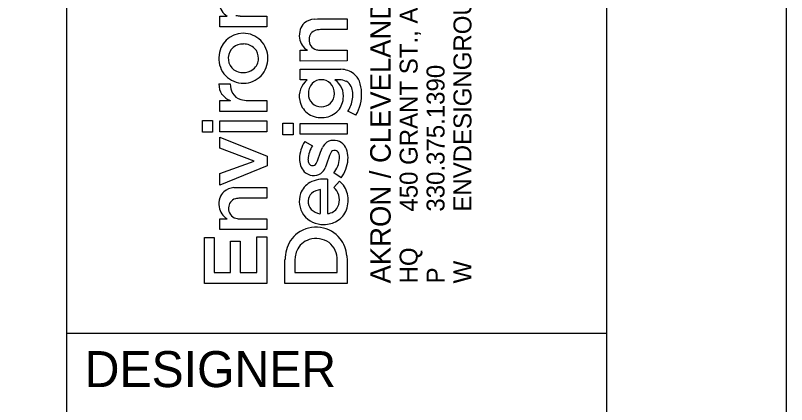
# Model space of a CAD drawing. Extents: x -0.3 to 34, y 0 to 22.
# Drawn here: x 31.857 to 34, y 2.302 to 3.382 of the extents above; entities that cross this region are included whole.
import ezdxf

# ---------------------------------------------------------------- set-up
doc = ezdxf.new("R2010")
doc.units = 0
for name, color, linetype in [('PM_X_CL_Double_Solid', 7, 'Continuous'), ('PM_X_CL_Pass_Proh_Lt', 7, 'Continuous'), ('PV_X_EOP', 7, 'Continuous')]:
    doc.layers.add(name, color=color, linetype=linetype)

msp = doc.modelspace()

# ---------------------------------------------------------------- linework, layer by layer
at = {"layer": 'PM_X_CL_Double_Solid'}
msp.add_lwpolyline([(0, 0), (34, 0), (34, 22), (0, 22)], close=True, dxfattribs=at)
at = {"layer": 'PM_X_CL_Pass_Proh_Lt'}
for p, q in [((32, 0.5), (32, 21.5)), ((32, 2.5), (33.5, 2.5))]:
    msp.add_line(p, q, dxfattribs=at)
msp.add_lwpolyline([(1.5, 21.5), (33.5, 21.5), (33.5, 0.5), (1.5, 0.5)], close=True, dxfattribs=at)
at = {"layer": 'PV_X_EOP'}
for p, q in [((32.4254, 3.3509), (32.4254, 3.3807)), ((32.4254, 3.3807), (32.4455, 3.3807)), ((32.4822, 3.3807), (32.5557, 3.3807)), ((32.5557, 3.3807), (32.5557, 3.351)), ((32.6878, 3.3722), (32.6963, 3.3727)), ((32.6963, 3.3727), (32.7792, 3.3727)), ((32.7792, 3.3727), (32.7792, 3.3429)), ((32.5557, 3.351), (32.4254, 3.3509)), ((32.7792, 3.3429), (32.7048, 3.3428)), ((32.6489, 3.2557), (32.6489, 3.2855)), ((32.6489, 3.2855), (32.669, 3.2855)), ((32.7057, 3.2855), (32.7791, 3.2855)), ((32.7791, 3.2855), (32.7792, 3.2558)), ((32.7792, 3.2558), (32.6489, 3.2557)), ((32.6489, 3.2034), (32.6489, 3.2332)), ((32.6489, 3.2332), (32.7524, 3.2332)), ((32.7524, 3.2332), (32.7619, 3.2329)), ((32.6684, 3.2034), (32.6489, 3.2034)), ((32.7576, 3.2036), (32.7449, 3.2036)), ((32.423, 3.1919), (32.4545, 3.1919)), ((32.4254, 3.1159), (32.4254, 3.1458)), ((32.4254, 3.1458), (32.4547, 3.1458)), ((32.5041, 3.1458), (32.5557, 3.1457)), ((32.5557, 3.1457), (32.5556, 3.1159)), ((32.5556, 3.1159), (32.4254, 3.1159)), ((32.8036, 3.1049), (32.7812, 3.116)), ((32.3771, 3.0582), (32.3771, 3.0903)), ((32.3771, 3.0903), (32.4054, 3.0903)), ((32.4054, 3.0903), (32.4054, 3.0582)), ((32.4254, 3.0594), (32.4254, 3.0893)), ((32.4254, 3.0893), (32.5557, 3.0893)), ((32.5557, 3.0893), (32.5557, 3.0594)), ((32.6005, 3.0511), (32.6005, 3.0832)), ((32.6005, 3.0832), (32.6289, 3.0832)), ((32.6289, 3.0832), (32.6289, 3.0511)), ((32.6489, 3.0523), (32.6489, 3.0822)), ((32.6489, 3.0822), (32.7792, 3.0822)), ((32.7792, 3.0822), (32.7792, 3.0523)), ((32.4054, 3.0582), (32.3771, 3.0582)), ((32.5557, 3.0594), (32.4254, 3.0594)), ((32.4254, 3.0133), (32.4254, 3.0446)), ((32.4254, 3.0446), (32.5567, 2.9913)), ((32.6289, 3.0511), (32.6005, 3.0511)), ((32.7792, 3.0523), (32.6489, 3.0523)), ((32.6615, 3.0321), (32.6827, 3.0203)), ((32.5212, 2.978), (32.4254, 3.0133)), ((32.6967, 2.9787), (32.7048, 3.0026)), ((32.7048, 3.0026), (32.7104, 3.0153)), ((32.7334, 3.001), (32.7298, 2.9933)), ((32.5567, 2.9913), (32.5567, 2.9644)), ((32.693, 2.9712), (32.6967, 2.9787)), ((32.7298, 2.9933), (32.7221, 2.9688)), ((32.4254, 2.9429), (32.5212, 2.978)), ((32.5567, 2.9644), (32.4254, 2.9109)), ((32.7221, 2.9688), (32.7182, 2.9592)), ((32.4254, 2.9109), (32.4254, 2.9429)), ((32.7621, 2.9314), (32.742, 2.9447)), ((32.7245, 2.9275), (32.7246, 2.8319)), ((32.7423, 2.9046), (32.7577, 2.922)), ((32.4644, 2.904), (32.4729, 2.9044)), ((32.4729, 2.9044), (32.5557, 2.9044)), ((32.5557, 2.9044), (32.5557, 2.8746)), ((32.7049, 2.8318), (32.7049, 2.8983)), ((32.5557, 2.8746), (32.4814, 2.8746)), ((32.7036, 2.8317), (32.7049, 2.8318)), ((32.4254, 2.7875), (32.4254, 2.8173)), ((32.4254, 2.8173), (32.4455, 2.8173)), ((32.4822, 2.8173), (32.5557, 2.8173)), ((32.5557, 2.8173), (32.5557, 2.7876)), ((32.5557, 2.7876), (32.4254, 2.7875)), ((32.383, 2.6379), (32.383, 2.766)), ((32.383, 2.766), (32.4101, 2.766)), ((32.4101, 2.766), (32.4101, 2.6683)), ((32.5286, 2.6683), (32.5286, 2.7672)), ((32.5286, 2.7672), (32.5557, 2.7672)), ((32.5557, 2.7672), (32.5557, 2.6379)), ((32.455, 2.6683), (32.455, 2.7549)), ((32.455, 2.7549), (32.4822, 2.7549)), ((32.4822, 2.7549), (32.4822, 2.6683)), ((32.6064, 2.638), (32.6064, 2.704)), ((32.6347, 2.7118), (32.6341, 2.7023)), ((32.6341, 2.7023), (32.6341, 2.6684)), ((32.7515, 2.6683), (32.7515, 2.7024)), ((32.7785, 2.715), (32.7792, 2.7021)), ((32.7792, 2.7021), (32.7792, 2.638)), ((32.4101, 2.6683), (32.455, 2.6683)), ((32.4822, 2.6683), (32.5286, 2.6683)), ((32.6341, 2.6684), (32.7515, 2.6683)), ((32.5557, 2.6379), (32.383, 2.6379)), ((32.7792, 2.638), (32.6064, 2.638))]:
    msp.add_line(p, q, dxfattribs=at)
for points in [[(32.4254, 3.3509), (32.4254, 3.3807), (32.4455, 3.3807)], [(32.4822, 3.3807), (32.5557, 3.3807), (32.5557, 3.351), (32.4254, 3.3509)], [(32.6878, 3.3722), (32.6963, 3.3727), (32.7792, 3.3727), (32.7792, 3.3429), (32.7048, 3.3428)], [(32.6489, 3.2557), (32.6489, 3.2855), (32.669, 3.2855)], [(32.7057, 3.2855), (32.7791, 3.2855), (32.7792, 3.2558), (32.6489, 3.2557)], [(32.6684, 3.2034), (32.6489, 3.2034), (32.6489, 3.2332), (32.7524, 3.2332), (32.7619, 3.2329)], [(32.7576, 3.2036), (32.7449, 3.2036)], [(32.423, 3.1919), (32.4545, 3.1919)], [(32.4254, 3.1159), (32.4254, 3.1458), (32.4547, 3.1458)], [(32.5041, 3.1458), (32.5557, 3.1457), (32.5556, 3.1159), (32.4254, 3.1159)], [(32.8036, 3.1049), (32.7812, 3.116)], [(32.6615, 3.0321), (32.6827, 3.0203)], [(32.693, 2.9712), (32.6967, 2.9787), (32.7048, 3.0026), (32.7104, 3.0153)], [(32.7334, 3.001), (32.7298, 2.9933), (32.7221, 2.9688), (32.7182, 2.9592)], [(32.7621, 2.9314), (32.742, 2.9447)], [(32.7245, 2.9275), (32.7246, 2.8319)], [(32.7423, 2.9046), (32.7577, 2.922)], [(32.4644, 2.904), (32.4729, 2.9044), (32.5557, 2.9044), (32.5557, 2.8746), (32.4814, 2.8746)], [(32.7036, 2.8317), (32.7049, 2.8318), (32.7049, 2.8983)], [(32.4254, 2.7875), (32.4254, 2.8173), (32.4455, 2.8173)], [(32.4822, 2.8173), (32.5557, 2.8173), (32.5557, 2.7876), (32.4254, 2.7875)], [(32.7785, 2.715), (32.7792, 2.7021), (32.7792, 2.638), (32.6064, 2.638)], [(32.6064, 2.638), (32.6064, 2.704)], [(32.6347, 2.7118), (32.6341, 2.7023), (32.6341, 2.6684), (32.7515, 2.6683), (32.7515, 2.7024)]]:
    msp.add_lwpolyline(points, dxfattribs=at)
for points in [[(32.3771, 3.0582), (32.3771, 3.0903), (32.4054, 3.0903), (32.4054, 3.0582)], [(32.4254, 3.0594), (32.4254, 3.0893), (32.5557, 3.0893), (32.5557, 3.0594)], [(32.6005, 3.0511), (32.6005, 3.0832), (32.6289, 3.0832), (32.6289, 3.0511)], [(32.6489, 3.0523), (32.6489, 3.0822), (32.7792, 3.0822), (32.7792, 3.0523)], [(32.4254, 2.9109), (32.4254, 2.9429), (32.5212, 2.978), (32.4254, 3.0133), (32.4254, 3.0446), (32.5567, 2.9913), (32.5567, 2.9644)], [(32.383, 2.6379), (32.383, 2.766), (32.4101, 2.766), (32.4101, 2.6683), (32.455, 2.6683), (32.455, 2.7549), (32.4822, 2.7549), (32.4822, 2.6683), (32.5286, 2.6683), (32.5286, 2.7672), (32.5557, 2.7672), (32.5557, 2.6379)]]:
    msp.add_lwpolyline(points, close=True, dxfattribs=at)
for centre, radius, start, end in [((32.4703, 3.4214), 0.0476, 188.9646, 238.6987), ((32.4703, 3.4214), 0.0476, 188.9646, 238.6987), ((32.4818, 3.4229), 0.0421, 254.0891, 270.5284), ((32.4818, 3.4229), 0.0421, 254.0891, 270.5284), ((32.6922, 3.3225), 0.0499, 94.9706, 130.2248), ((32.6922, 3.3225), 0.0499, 94.9706, 130.2248), ((32.7022, 3.3264), 0.056, 162.274, 187.7917), ((32.7022, 3.3264), 0.056, 162.274, 187.7917), ((32.6869, 3.3309), 0.0402, 132.2238, 161.6823), ((32.6869, 3.3309), 0.0402, 132.2238, 161.6823), ((32.7045, 3.2968), 0.046, 89.6051, 105.3303), ((32.7045, 3.2968), 0.046, 89.6051, 105.3303), ((32.4901, 3.2654), 0.0674, 89.8476, 179.6405), ((32.4901, 3.2654), 0.0674, 89.8476, 179.6405), ((32.4906, 3.2647), 0.0681, 359.5401, 90.2114), ((32.4906, 3.2647), 0.0681, 359.5401, 90.2114), ((32.6983, 3.3169), 0.025, 103.6868, 182.214), ((32.6983, 3.3169), 0.025, 103.6868, 182.214), ((32.4892, 3.2626), 0.0404, 87.0481, 175.5726), ((32.4892, 3.2626), 0.0404, 87.0481, 175.5726), ((32.492, 3.26), 0.043, 45.8426, 90.9801), ((32.492, 3.26), 0.043, 45.8426, 90.9801), ((32.6937, 3.3262), 0.0476, 188.9646, 238.6987), ((32.6937, 3.3262), 0.0476, 188.9646, 238.6987), ((32.7008, 3.3138), 0.0276, 175.5844, 255.1382), ((32.7008, 3.3138), 0.0276, 175.5844, 255.1382), ((32.4946, 3.2642), 0.0382, 357.8857, 44.159), ((32.4946, 3.2642), 0.0382, 357.8857, 44.159), ((32.7053, 3.3277), 0.0421, 254.0891, 270.5284), ((32.7053, 3.3277), 0.0421, 254.0891, 270.5284), ((32.4908, 3.2621), 0.0682, 176.8344, 270.4038), ((32.4908, 3.2621), 0.0682, 176.8344, 270.4038), ((32.4873, 3.2625), 0.0385, 175.1538, 221.1471), ((32.4873, 3.2625), 0.0385, 175.1538, 221.1471), ((32.4912, 3.2614), 0.0675, 270.0624, 2.3776), ((32.4912, 3.2614), 0.0675, 270.0624, 2.3776), ((32.4945, 3.2632), 0.0383, 308.2894, 359.4347), ((32.4945, 3.2632), 0.0383, 308.2894, 359.4347), ((32.4892, 3.2661), 0.0423, 223.0999, 268.8089), ((32.4892, 3.2661), 0.0423, 223.0999, 268.8089), ((32.491, 3.2679), 0.0442, 266.5651, 308.0608), ((32.491, 3.2679), 0.0442, 266.5651, 308.0608), ((32.7591, 3.1679), 0.065, 53.4034, 87.4906), ((32.7591, 3.1679), 0.065, 53.4034, 87.4906), ((32.7652, 3.1804), 0.0514, 21.6075, 50.5577), ((32.7652, 3.1804), 0.0514, 21.6075, 50.5577), ((32.7029, 3.1581), 0.0569, 127.3748, 192.2247), ((32.7029, 3.1581), 0.0569, 127.3748, 192.2247), ((32.7114, 3.166), 0.0401, 137.4674, 182.3324), ((32.7114, 3.166), 0.0401, 137.4674, 182.3324), ((32.7069, 3.1693), 0.0346, 88.473, 136.4256), ((32.7069, 3.1693), 0.0346, 88.473, 136.4256), ((32.7081, 3.1696), 0.0342, 44.2719, 90.4762), ((32.7081, 3.1696), 0.0342, 44.2719, 90.4762), ((32.7037, 3.166), 0.04, 358.5714, 43.5376), ((32.7037, 3.166), 0.04, 358.5714, 43.5376), ((32.7142, 3.1583), 0.0547, 352.1125, 55.923), ((32.7142, 3.1583), 0.0547, 352.1125, 55.923), ((32.7567, 3.1572), 0.0463, 65.0169, 88.8011), ((32.7567, 3.1572), 0.0463, 65.0169, 88.8011), ((32.7626, 3.1716), 0.0309, 26.2681, 63.803), ((32.7626, 3.1716), 0.0309, 26.2681, 63.803), ((32.7307, 3.1671), 0.0884, 1.1514, 21.3627), ((32.7307, 3.1671), 0.0884, 1.1514, 21.3627), ((32.4662, 3.1888), 0.0433, 175.8731, 216.3475), ((32.4662, 3.1888), 0.0433, 175.8731, 216.3475), ((32.5009, 3.1895), 0.0464, 176.9688, 209.6064), ((32.5009, 3.1895), 0.0464, 176.9688, 209.6064), ((32.7357, 3.1615), 0.0595, 349.3073, 23.4307), ((32.7357, 3.1615), 0.0595, 349.3073, 23.4307), ((32.4747, 3.1972), 0.0551, 218.0981, 248.7907), ((32.4747, 3.1972), 0.0551, 218.0981, 248.7907), ((32.4951, 3.1881), 0.0408, 211.9447, 253.2028), ((32.4951, 3.1881), 0.0408, 211.9447, 253.2028), ((32.7065, 3.1637), 0.0351, 178.8821, 271.0837), ((32.7065, 3.1637), 0.0351, 178.8821, 271.0837), ((32.7082, 3.164), 0.0355, 268.2788, 1.5502), ((32.7082, 3.164), 0.0355, 268.2788, 1.5502), ((32.7099, 3.1571), 0.0589, 313.742, 353.8554), ((32.7099, 3.1571), 0.0589, 313.742, 353.8554), ((32.7074, 3.1633), 0.0877, 327.3149, 351.5748), ((32.7074, 3.1633), 0.0877, 327.3149, 351.5748), ((32.7054, 3.1624), 0.1138, 329.6388, 3.26), ((32.7054, 3.1624), 0.1138, 329.6388, 3.26), ((32.5047, 3.2165), 0.0707, 252.4655, 269.573), ((32.5047, 3.2165), 0.0707, 252.4655, 269.573), ((32.7046, 3.157), 0.0584, 190.7518, 231.2892), ((32.7046, 3.157), 0.0584, 190.7518, 231.2892), ((32.7063, 3.1611), 0.0627, 232.4606, 272.5902), ((32.7063, 3.1611), 0.0627, 232.4606, 272.5902), ((32.7095, 3.159), 0.0605, 269.6361, 312.7088), ((32.7095, 3.159), 0.0605, 269.6361, 312.7088), ((32.7364, 2.9826), 0.0897, 146.531, 178.7571), ((32.7364, 2.9826), 0.0897, 146.531, 178.7571), ((32.7466, 2.9971), 0.0405, 125.5118, 153.4159), ((32.7466, 2.9971), 0.0405, 125.5118, 153.4159), ((32.7406, 3.0026), 0.0326, 80.1719, 122.5197), ((32.7406, 3.0026), 0.0326, 80.1719, 122.5197), ((32.7428, 2.9982), 0.0367, 47.7934, 84.6892), ((32.7428, 2.9982), 0.0367, 47.7934, 84.6892), ((32.7379, 2.9946), 0.0427, 14.9966, 46.2063), ((32.7379, 2.9946), 0.0427, 14.9966, 46.2063), ((32.7452, 2.9789), 0.0749, 146.5112, 176.9101), ((32.7452, 2.9789), 0.0749, 146.5112, 176.9101), ((32.7438, 2.9963), 0.0114, 76.6609, 155.7053), ((32.7438, 2.9963), 0.0114, 76.6609, 155.7053), ((32.744, 2.9951), 0.0126, 21.5098, 78.5262), ((32.744, 2.9951), 0.0126, 21.5098, 78.5262), ((32.7259, 2.9877), 0.0321, 354.5726, 22.068), ((32.7259, 2.9877), 0.0321, 354.5726, 22.068), ((32.7104, 2.9867), 0.0712, 355.8306, 15.3914), ((32.7104, 2.9867), 0.0712, 355.8306, 15.3914), ((32.6967, 2.9824), 0.0501, 177.5366, 222.7932), ((32.6967, 2.9824), 0.0501, 177.5366, 222.7932), ((32.6931, 2.9823), 0.0228, 178.4747, 211.0868), ((32.6931, 2.9823), 0.0228, 178.4747, 211.0868), ((32.6825, 2.9915), 0.0757, 321.811, 354.7969), ((32.6825, 2.9915), 0.0757, 321.811, 354.7969), ((32.6895, 2.9882), 0.0922, 321.9777, 355.8738), ((32.6895, 2.9882), 0.0922, 321.9777, 355.8738), ((32.6833, 2.9767), 0.0115, 212.2368, 268.3777), ((32.6833, 2.9767), 0.0115, 212.2368, 268.3777), ((32.6834, 2.9759), 0.0107, 267.716, 333.7337), ((32.6834, 2.9759), 0.0107, 267.716, 333.7337), ((32.681, 2.9758), 0.0408, 308.0877, 335.9874), ((32.681, 2.9758), 0.0408, 308.0877, 335.9874), ((32.686, 2.9753), 0.0375, 225.9854, 302.4797), ((32.686, 2.9753), 0.0375, 225.9854, 302.4797), ((32.7024, 2.8691), 0.0558, 118.8308, 160.6244), ((32.7024, 2.8691), 0.0558, 118.8308, 160.6244), ((32.7152, 2.8441), 0.0838, 83.615, 118.2876), ((32.7152, 2.8441), 0.0838, 83.615, 118.2876), ((32.7174, 2.8717), 0.0644, 13.5336, 51.3615), ((32.7174, 2.8717), 0.0644, 13.5336, 51.3615), ((32.4687, 2.8543), 0.0499, 94.9696, 130.2225), ((32.4687, 2.8543), 0.0499, 94.9696, 130.2225), ((32.7079, 2.8561), 0.0424, 94.008, 130.8817), ((32.7079, 2.8561), 0.0424, 94.008, 130.8817), ((32.7038, 2.8656), 0.0549, 19.0357, 45.4406), ((32.7038, 2.8656), 0.0549, 19.0357, 45.4406), ((32.4787, 2.8582), 0.056, 162.2736, 187.7919), ((32.4787, 2.8582), 0.056, 162.2736, 187.7919), ((32.4635, 2.8626), 0.0402, 132.2219, 161.6818), ((32.4635, 2.8626), 0.0402, 132.2219, 161.6818), ((32.4748, 2.8487), 0.025, 103.6865, 182.2187), ((32.4748, 2.8487), 0.025, 103.6865, 182.2187), ((32.4811, 2.8286), 0.046, 89.6049, 105.3284), ((32.4811, 2.8286), 0.046, 89.6049, 105.3284), ((32.7104, 2.8661), 0.0644, 160.5201, 215.7831), ((32.7104, 2.8661), 0.0644, 160.5201, 215.7831), ((32.7005, 2.8663), 0.0298, 132.9851, 177.179), ((32.7005, 2.8663), 0.0298, 132.9851, 177.179), ((32.7107, 2.8697), 0.047, 344.6059, 17.007), ((32.7107, 2.8697), 0.047, 344.6059, 17.007), ((32.7064, 2.8692), 0.0758, 339.3542, 13.3785), ((32.7064, 2.8692), 0.0758, 339.3542, 13.3785), ((32.4703, 2.858), 0.0476, 188.962, 238.7037), ((32.4703, 2.858), 0.0476, 188.962, 238.7037), ((32.7017, 2.865), 0.0311, 175.0013, 223.283), ((32.7017, 2.865), 0.0311, 175.0013, 223.283), ((32.7224, 2.8671), 0.035, 288.0077, 343.5508), ((32.7224, 2.8671), 0.035, 288.0077, 343.5508), ((32.4773, 2.8456), 0.0276, 175.5854, 255.1439), ((32.4773, 2.8456), 0.0276, 175.5854, 255.1439), ((32.7125, 2.8705), 0.0687, 217.7452, 271.6543), ((32.7125, 2.8705), 0.0687, 217.7452, 271.6543), ((32.7089, 2.8736), 0.0423, 225.0619, 262.7974), ((32.7089, 2.8736), 0.0423, 225.0619, 262.7974), ((32.7247, 2.8522), 0.0202, 269.7003, 294.8711), ((32.7247, 2.8522), 0.0202, 269.7003, 294.8711), ((32.7189, 2.8652), 0.0626, 300.9427, 338.7323), ((32.7189, 2.8652), 0.0626, 300.9427, 338.7323), ((32.4818, 2.8595), 0.0422, 254.0916, 270.5284), ((32.4818, 2.8595), 0.0422, 254.0916, 270.5284), ((32.7155, 2.8724), 0.0706, 269.2048, 300.3341), ((32.7155, 2.8724), 0.0706, 269.2048, 300.3341), ((32.6923, 2.7079), 0.0864, 81.194, 125.9984), ((32.6923, 2.7079), 0.0864, 81.194, 125.9984), ((32.6946, 2.7113), 0.0827, 37.8521, 82.402), ((32.6946, 2.7113), 0.0827, 37.8521, 82.402), ((32.6939, 2.7089), 0.0865, 127.2362, 165.148), ((32.6939, 2.7089), 0.0865, 127.2362, 165.148), ((32.6889, 2.7078), 0.054, 106.1881, 157.3861), ((32.6889, 2.7078), 0.054, 106.1881, 157.3861), ((32.6928, 2.6986), 0.0639, 55.6727, 107.2093), ((32.6928, 2.6986), 0.0639, 55.6727, 107.2093), ((32.6929, 2.705), 0.0587, 357.4662, 52.2665), ((32.6929, 2.705), 0.0587, 357.4662, 52.2665), ((32.6859, 2.7057), 0.0931, 5.7333, 37.304), ((32.6859, 2.7057), 0.0931, 5.7333, 37.304), ((32.7143, 2.7028), 0.1078, 164.7861, 179.3704), ((32.7143, 2.7028), 0.1078, 164.7861, 179.3704), ((32.6983, 2.7039), 0.0641, 157.3571, 172.9275), ((32.6983, 2.7039), 0.0641, 157.3571, 172.9275)]:
    msp.add_arc(centre, radius, start, end, dxfattribs=at)

# ---------------------------------------------------------------- texts
for s, height, p in [('450 GRANT ST., AKRON, OH  44311', 0.049846, (32.9749, 2.8374)), ('AKRON / CLEVELAND / COLUMBUS', 0.056969, (32.9001, 2.638)), ('ENVDESIGNGROUP.COM', 0.049846, (33.1244, 2.8374)), ('330.375.1390', 0.049846, (33.0497, 2.8374)), ('HQ ', 0.04985, (32.9749, 2.638)), ('W', 0.0498, (33.1244, 2.638)), ('P', 0.0498, (33.0497, 2.638))]:
    msp.add_text(s, height=height, rotation=90, dxfattribs=at).set_placement(p)
msp.add_text('DESIGNER', height=0.1, dxfattribs=at).set_placement((32.05, 2.35))

doc.saveas('drawing.dxf')
